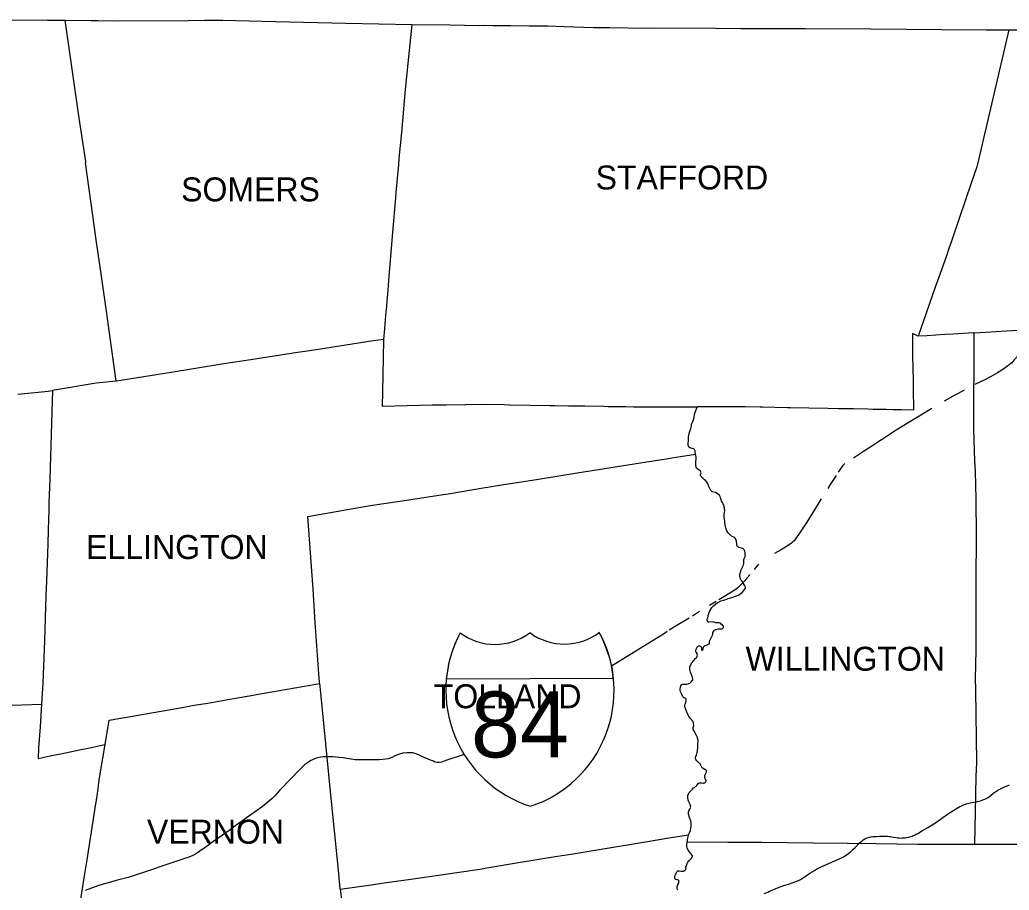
# Model space of a CAD drawing. Extents: x 0 to 2603, y -226 to 830.
# Drawn here: x 231.5 to 287.2, y 653.4 to 702.5 of the extents above; entities that cross this region are included whole.
import ezdxf

# ---------------------------------------------------------------- set-up
doc = ezdxf.new("R2010")
doc.units = 0
for name, color, linetype in [('CT_TSH_Map_Districts', 7, 'Continuous'), ('CT_TSH_Map_Interstate_Roads', 7, 'Continuous'), ('CT_TSH_Map_Town_Limits', 7, 'Continuous'), ('CT_TSH_Map_Town_Text', 7, 'Continuous'), ('CT_TSH_Map_US_and_State_Routes', 7, 'Continuous')]:
    doc.layers.add(name, color=color, linetype=linetype)

msp = doc.modelspace()

# ---------------------------------------------------------------- linework, layer by layer
at = {"layer": 'CT_TSH_Map_Districts'}
for points in [[(285.263, 684.866), (285.933, 684.911), (287.104, 684.983), (287.764, 685.023), (289.085, 685.105), (289.205, 685.102), (289.289, 685.108), (289.862, 685.118), (294.917, 685.193), (296.698, 685.197)], [(285.263, 684.866), (285.247, 682.571), (285.241, 681.474), (285.241, 680.031), (285.233, 679.443), (285.299, 677.651), (285.326, 677.079), (285.377, 675.496), (285.38, 673.452), (285.382, 672.739), (285.377, 671.584), (285.377, 668.972), (285.37, 668.249), (285.375, 667.631), (285.368, 666.987), (285.329, 665.367), (285.34, 664.78), (285.344, 664.739), (285.4, 660.656), (285.377, 659.862), (285.336, 657.85), (285.293, 656.032)], [(269.09, 656.152), (269.106, 656.26), (269.122, 656.315), (269.144, 656.453), (269.17, 656.564), (269.174, 656.574)], [(268.561, 653.446), (268.542, 653.535), (268.528, 653.59), (268.531, 653.653), (268.548, 653.719), (268.573, 653.776), (268.622, 653.858), (268.634, 653.91), (268.627, 653.991), (268.606, 654.015), (268.555, 654.032), (268.482, 654.044), (268.454, 654.054), (268.42, 654.089), (268.407, 654.112), (268.398, 654.16), (268.403, 654.233), (268.433, 654.324), (268.468, 654.405), (268.516, 654.477), (268.559, 654.521), (268.577, 654.535), (268.612, 654.548), (268.638, 654.55), (268.753, 654.518), (268.832, 654.514), (268.885, 654.522), (268.951, 654.551), (268.988, 654.578), (269.019, 654.626), (269.033, 654.689), (269.03, 654.752), (269.051, 654.842), (269.1, 654.953), (269.111, 654.992), (269.133, 655.031), (269.188, 655.108), (269.241, 655.17), (269.343, 655.253), (269.386, 655.31), (269.403, 655.349), (269.397, 655.385), (269.387, 655.405), (269.317, 655.496), (269.267, 655.552), (269.204, 655.631), (269.129, 655.745), (269.095, 655.838), (269.078, 655.916), (269.075, 656.006), (269.09, 656.152)], [(285.293, 656.032), (284.403, 656.034), (282.106, 656.032), (279.722, 656.059), (278.191, 656.087), (278.142, 656.084), (276.191, 656.107), (273.285, 656.144), (271.395, 656.143), (269.09, 656.152)]]:
    msp.add_lwpolyline(points, dxfattribs=at)
at = {"layer": 'CT_TSH_Map_Interstate_Roads'}
for p, q in [((264.952, 665.379), (255.52, 665.339)), ((242.107, 655.992), (241.385, 655.487)), ((240.221, 655.049), (239.307, 654.741)), ((237.988, 654.302), (237.872, 654.259)), ((238.627, 654.513), (237.988, 654.302)), ((236.462, 653.87), (235.985, 653.729)), ((236.911, 653.99), (236.462, 653.87))]:
    msp.add_line(p, q, dxfattribs=at)
for points in [[(288.632, 685.126), (288.156, 684.322), (287.757, 683.642), (287.653, 683.489), (287.537, 683.342), (287.478, 683.275), (287.37, 683.171), (287.172, 683.014), (287.023, 682.893), (286.838, 682.761), (286.581, 682.61), (286.2, 682.399)], [(286.2, 682.399), (285.871, 682.228), (285.314, 681.961)], [(284.706, 681.636), (284.363, 681.452), (284.185, 681.352), (283.59, 681.017)], [(282.893, 680.61), (282.792, 680.554), (282.46, 680.351), (282.022, 680.088), (281.561, 679.804), (280.884, 679.377), (280.378, 679.053), (279.74, 678.637), (279.497, 678.479)], [(279.497, 678.479), (279.249, 678.318), (279.045, 678.186), (278.69, 677.954), (278.467, 677.814)], [(277.985, 677.508), (277.959, 677.49), (277.905, 677.439), (277.867, 677.393), (277.81, 677.322), (277.731, 677.207), (277.607, 677.017)], [(277.489, 676.833), (277.164, 676.324), (277.027, 676.103)], [(276.649, 675.505), (276.323, 674.989), (275.833, 674.203)], [(275.833, 674.203), (275.434, 673.582), (275.395, 673.521), (275.212, 673.265), (275.124, 673.153), (275.061, 673.087), (274.974, 673.009), (274.841, 672.911), (274.692, 672.82), (274.394, 672.646), (274.015, 672.435)], [(273.11, 671.831), (272.87, 671.531)], [(272.646, 671.256), (272.465, 671.033), (272.341, 670.896)], [(271.851, 670.425), (271.595, 670.255), (271.067, 669.937)], [(272.341, 670.896), (272.221, 670.761), (272.071, 670.611), (271.971, 670.524), (271.851, 670.425)], [(271.067, 669.937), (270.873, 669.815)], [(270.725, 669.727), (270.346, 669.5)], [(269.201, 668.788), (268.52, 668.368)], [(269.794, 669.154), (269.395, 668.908)], [(268.52, 668.368), (268.086, 668.1)], [(267.811, 667.93), (264.836, 666.086)], [(267.977, 668.033), (267.811, 667.93)], [(248.452, 660.95), (248.242, 660.906), (248.142, 660.875)], [(248.958, 660.965), (248.775, 660.963), (248.588, 660.964), (248.452, 660.95)], [(252.349, 660.89), (252.244, 660.862), (252.093, 660.83), (251.939, 660.813), (251.729, 660.8), (251.558, 660.799), (251.07, 660.795), (250.588, 660.791), (250.454, 660.79), (250.383, 660.8), (250.277, 660.819), (250.039, 660.857), (249.896, 660.881), (249.706, 660.904), (249.47, 660.931), (249.28, 660.949), (249.12, 660.961), (249.013, 660.966), (248.958, 660.965)], [(253.821, 661.131), (253.625, 661.185), (253.477, 661.202), (253.319, 661.197), (253.07, 661.166), (252.829, 661.097), (252.609, 661.021), (252.495, 660.955), (252.349, 660.89)], [(254.634, 660.786), (254.269, 660.937), (253.821, 661.131)], [(256.525, 661.099), (255.552, 660.78), (255.243, 660.673), (255.113, 660.652), (254.998, 660.654), (254.897, 660.675), (254.79, 660.72), (254.634, 660.786)], [(247.701, 660.629), (247.533, 660.512), (247.466, 660.457), (247.406, 660.403), (247.25, 660.24), (246.759, 659.726), (246.126, 659.063), (245.848, 658.767), (245.683, 658.606)], [(248.142, 660.875), (248.057, 660.842), (247.969, 660.804), (247.882, 660.756), (247.804, 660.7), (247.701, 660.629)], [(245.683, 658.606), (245.617, 658.544), (245.462, 658.405), (245.262, 658.244), (245.14, 658.151), (244.814, 657.918), (244.567, 657.743), (244.262, 657.525)], [(244.262, 657.525), (244.037, 657.366), (243.787, 657.187), (243.524, 656.999), (243.329, 656.86)], [(243.329, 656.86), (242.901, 656.558), (242.708, 656.415)], [(242.708, 656.415), (242.364, 656.172), (242.107, 655.992)], [(241.385, 655.487), (241.23, 655.4), (241.109, 655.347), (240.889, 655.276), (240.221, 655.049)], [(237.872, 654.259), (237.587, 654.166), (236.911, 653.99)], [(239.307, 654.741), (239.12, 654.677), (238.627, 654.513)], [(235.985, 653.729), (235.614, 653.604), (235.367, 653.51), (235.17, 653.427)]]:
    msp.add_lwpolyline(points, dxfattribs=at)
for centre, radius, start, end in [((262.356, 664.719), 6.864, 151.8748, 252.2637), ((262.365, 664.715), 6.874, 151.8748, 174.7861), ((258.258, 670.571), 3.265, 233.2263, 307.1377), ((262.174, 670.589), 3.264, 233.3979, 307.1378), ((258.113, 664.699), 6.864, 288.272, 28.6609), ((258.122, 664.695), 6.864, 5.7168, 28.6609)]:
    msp.add_arc(centre, radius, start, end, dxfattribs=at)
at = {"layer": 'CT_TSH_Map_Town_Limits'}
for points in [[(216.957, 700.307), (219.751, 700.248), (221.29, 700.214), (222.262, 700.994), (222.922, 701.493), (226.979, 702.07), (230.107, 702.52), (230.118, 702.52), (233.045, 702.499), (234.019, 702.492)], [(234.019, 702.492), (235.495, 702.482), (235.713, 702.488), (235.728, 702.475), (235.876, 702.474), (237.005, 702.454), (240.968, 702.482), (241.914, 702.504), (242.915, 702.501), (242.925, 702.501), (245.895, 702.424), (249.856, 702.327), (253.576, 702.255)], [(234.019, 702.492), (234.041, 702.363), (234.355, 700.135), (234.814, 696.978), (235.185, 694.533), (235.191, 694.462)], [(253.576, 702.255), (253.206, 698.582), (252.99, 696.168), (252.849, 694.691), (252.851, 694.527)], [(253.576, 702.255), (255.71, 702.227), (257.378, 702.206), (257.592, 702.208), (258.165, 702.202), (258.908, 702.192), (258.911, 702.192), (259.143, 702.193), (260.204, 702.179), (261.248, 702.172), (262.172, 702.147), (263.839, 702.087), (264.735, 702.087), (266.786, 702.054), (266.947, 702.06), (270.692, 702.039), (272.118, 702.035), (275.574, 702.027), (275.761, 702.026), (279.456, 702.002), (283.438, 701.981), (285.954, 701.963), (287.227, 701.95)], [(287.227, 701.95), (285.533, 694.694)], [(287.227, 701.95), (288.33, 701.956), (293.654, 701.922), (296.827, 701.891), (298.059, 701.91), (298.257, 701.902), (299.351, 701.838), (299.357, 701.838), (299.361, 701.837), (300.965, 701.762), (301.321, 701.764), (301.732, 701.741), (305.24, 701.567)], [(236.912, 682.141), (236.761, 683.229), (236.483, 685.275), (236.36, 686.085), (236.1, 687.926), (235.768, 690.242), (235.695, 690.806), (235.191, 694.462)], [(251.99, 684.503), (252.048, 685.094), (252.056, 685.123), (252.064, 685.162), (252.137, 686.047), (252.162, 686.361), (252.188, 686.665), (252.242, 687.282), (252.306, 688.063), (252.507, 690.529), (252.667, 692.485), (252.691, 692.78), (252.742, 693.367), (252.768, 693.581), (252.843, 694.343), (252.851, 694.527)], [(285.533, 694.694), (285.458, 694.375), (285.415, 694.231), (285.126, 693.368), (284.418, 691.254), (284.318, 690.979), (284.192, 690.606), (283.97, 689.976), (283.85, 689.629), (283.713, 689.215), (283.636, 689.011), (283.343, 688.167), (283.082, 687.439), (282.572, 685.978), (282.121, 684.682)], [(285.263, 684.866), (285.933, 684.911), (287.104, 684.983), (287.764, 685.023), (289.085, 685.105), (289.205, 685.102), (289.289, 685.108), (289.862, 685.118), (294.917, 685.193), (296.698, 685.197)], [(251.99, 684.503), (251.393, 684.414), (248.309, 683.941), (247.42, 683.8), (247.126, 683.756), (244.503, 683.357), (242.971, 683.118), (241.272, 682.841), (240.01, 682.638), (236.938, 682.14), (236.912, 682.141)], [(251.99, 684.503), (251.987, 684.453), (251.946, 682.502), (251.927, 681.539), (251.906, 680.739), (254.73, 680.816), (255.517, 680.822), (256.59, 680.825), (256.628, 680.831), (257.685, 680.855), (258.8, 680.825), (259.077, 680.813), (261.351, 680.782), (261.635, 680.775), (262.409, 680.764), (262.715, 680.757), (263.332, 680.75), (264.408, 680.731), (264.64, 680.724), (265.633, 680.712), (266.071, 680.702), (266.137, 680.705), (266.51, 680.703), (267.583, 680.708), (269.508, 680.706), (269.655, 680.709)], [(282.121, 684.682), (281.795, 684.837), (281.804, 684.234), (281.805, 684.037), (281.805, 683.382), (281.818, 683.088), (281.819, 682.877), (281.82, 682.573), (281.832, 682.466), (281.839, 681.918), (281.84, 681.721), (281.855, 680.512), (281.171, 680.526), (280.708, 680.533), (280.309, 680.541), (279.576, 680.558), (279.288, 680.563), (278.468, 680.579), (278.414, 680.578), (277.626, 680.595), (277.016, 680.609), (275.959, 680.625), (274.927, 680.647), (274.761, 680.65), (273.344, 680.676), (273.213, 680.682), (272.369, 680.697), (271.99, 680.691), (270.901, 680.702), (269.655, 680.709)], [(285.263, 684.866), (284.065, 684.797), (283.614, 684.769), (282.602, 684.711), (282.121, 684.682)], [(285.263, 684.866), (285.247, 682.571), (285.241, 681.474), (285.241, 680.031), (285.233, 679.443), (285.299, 677.651), (285.326, 677.079), (285.377, 675.496), (285.38, 673.452), (285.382, 672.739), (285.377, 671.584), (285.377, 668.972), (285.37, 668.249), (285.375, 667.631), (285.368, 666.987), (285.329, 665.367), (285.34, 664.78), (285.344, 664.739), (285.4, 660.656), (285.377, 659.862), (285.336, 657.85), (285.293, 656.032)], [(236.912, 682.141), (235.787, 682.025), (233.319, 681.617)], [(231.371, 681.411), (233.07, 681.587), (233.319, 681.617)], [(233.319, 681.617), (233.304, 681.031), (233.168, 676.635), (233.124, 675.271), (233.113, 674.884), (233.071, 673.775), (233.05, 672.96), (232.984, 670.881), (232.951, 670.061), (232.867, 667.499), (232.816, 666.088), (232.795, 665.59), (232.778, 665.13), (232.702, 663.937)], [(269.655, 680.709), (269.598, 680.574), (269.491, 680.277), (269.482, 680.248), (269.465, 680.14), (269.465, 680.082), (269.457, 680.026), (269.44, 679.958), (269.396, 679.849), (269.337, 679.746), (269.32, 679.701), (269.318, 679.635), (269.265, 679.4), (269.222, 679.304), (269.197, 679.182), (269.165, 679.084), (269.151, 679.012), (269.158, 678.783), (269.127, 678.654), (269.14, 678.551), (269.154, 678.495), (269.188, 678.442), (269.241, 678.399), (269.364, 678.379), (269.428, 678.359), (269.474, 678.331), (269.488, 678.318), (269.512, 678.285), (269.523, 678.236), (269.525, 678.172), (269.536, 678.106), (269.558, 678.039)], [(248.386, 665.112), (248.377, 665.185), (248.336, 665.64), (248.135, 668.533), (248.008, 670.415), (247.718, 674.519), (251.225, 675.14), (252.906, 675.391), (254.009, 675.551), (255.09, 675.715), (255.621, 675.793), (257.707, 676.146), (257.864, 676.167), (258.275, 676.237), (260.612, 676.603), (263.006, 676.992), (263.253, 677.034), (264.463, 677.222), (265.16, 677.336), (265.756, 677.43), (267.43, 677.695), (267.687, 677.738), (267.939, 677.775), (268.228, 677.827), (268.715, 677.899), (269.558, 678.039)], [(270.951, 675.652), (270.91, 675.722), (270.831, 675.781), (270.734, 675.845), (270.689, 675.864), (270.528, 675.91), (270.491, 675.928), (270.448, 675.96), (270.429, 675.987), (270.376, 676.088), (270.314, 676.202), (270.276, 676.315), (270.242, 676.396), (270.202, 676.461), (270.147, 676.521), (270.072, 676.589), (270.041, 676.626), (270.014, 676.649), (269.988, 676.678), (269.924, 676.722), (269.9, 676.747), (269.867, 676.796), (269.848, 676.842), (269.848, 676.878), (269.877, 676.985), (269.872, 677.015), (269.86, 677.042), (269.839, 677.069), (269.759, 677.142), (269.719, 677.168), (269.665, 677.213), (269.647, 677.239), (269.612, 677.302), (269.587, 677.385), (269.583, 677.478), (269.584, 677.604), (269.597, 677.764), (269.595, 677.876), (269.585, 677.917), (269.558, 678.039)], [(270.53, 668.573), (270.339, 668.556), (270.294, 668.566), (270.27, 668.579), (270.241, 668.641), (270.231, 668.666), (270.233, 668.727), (270.246, 668.767), (270.256, 668.829), (270.278, 668.886), (270.285, 668.927), (270.335, 669.11), (270.368, 669.198), (270.424, 669.294), (270.51, 669.411), (270.586, 669.484), (270.81, 669.661), (270.86, 669.689), (270.987, 669.754), (271.172, 669.808), (271.215, 669.813), (271.324, 669.85), (271.416, 669.889), (271.616, 669.944), (271.767, 670.004), (271.938, 670.059), (271.988, 670.082), (272.119, 670.173), (272.193, 670.235), (272.292, 670.343), (272.352, 670.43), (272.378, 670.479), (272.382, 670.526), (272.373, 670.568), (272.337, 670.641), (272.268, 670.732), (272.171, 670.888), (272.15, 670.913), (272.125, 670.953), (272.106, 671.001), (272.08, 671.075), (272.068, 671.138), (272.069, 671.239), (272.101, 671.375), (272.142, 671.503), (272.255, 671.739), (272.281, 671.811), (272.288, 671.854), (272.294, 671.963), (272.289, 672.043), (272.291, 672.101), (272.305, 672.151), (272.355, 672.223), (272.371, 672.27), (272.371, 672.297), (272.36, 672.352), (272.359, 672.419), (272.365, 672.453), (272.362, 672.489), (272.341, 672.571), (272.306, 672.639), (272.274, 672.679), (272.223, 672.713), (272.156, 672.739), (272.012, 672.769), (271.982, 672.787), (271.944, 672.819), (271.922, 672.844), (271.901, 672.912), (271.9, 672.956), (271.875, 673.126), (271.854, 673.189), (271.846, 673.231), (271.806, 673.293), (271.761, 673.329), (271.68, 673.366), (271.599, 673.412), (271.53, 673.472), (271.411, 673.604), (271.356, 673.678), (271.342, 673.718), (271.315, 673.753), (271.268, 673.876), (271.254, 673.963), (271.235, 674.053), (271.228, 674.176), (271.216, 674.264), (271.201, 674.347), (271.18, 674.487), (271.179, 674.666), (271.205, 674.747), (271.215, 674.826), (271.195, 674.995), (271.181, 675.039), (271.161, 675.13), (271.122, 675.232), (271.084, 675.314), (271.039, 675.392), (270.988, 675.52), (270.981, 675.562), (270.951, 675.652)], [(268.994, 664.266), (268.893, 664.31), (268.865, 664.343), (268.838, 664.387), (268.749, 664.583), (268.741, 664.61), (268.715, 664.658), (268.707, 664.694), (268.707, 664.763), (268.725, 664.916), (268.746, 664.976), (268.775, 665.029), (268.802, 665.054), (268.849, 665.066), (269.086, 665.067), (269.154, 665.076), (269.196, 665.095), (269.25, 665.124), (269.341, 665.212), (269.386, 665.278), (269.407, 665.31), (269.407, 665.344), (269.393, 665.467), (269.386, 665.5), (269.318, 665.641), (269.284, 665.737), (269.246, 665.893), (269.238, 665.984), (269.246, 666.048), (269.283, 666.141), (269.364, 666.264), (269.456, 666.378), (269.591, 666.533), (269.618, 666.556), (269.635, 666.586), (269.662, 666.648), (269.672, 666.708), (269.668, 666.737), (269.651, 666.786), (269.619, 666.848), (269.584, 666.895), (269.578, 666.925), (269.576, 666.976), (269.606, 667.043), (269.646, 667.121), (269.686, 667.18), (269.73, 667.223), (269.754, 667.229), (269.799, 667.223), (269.848, 667.205), (269.87, 667.187), (269.886, 667.166), (269.9, 667.112), (269.895, 667.04), (269.899, 667.015), (269.912, 666.997), (269.932, 666.983), (269.952, 666.98), (269.965, 666.985), (269.98, 667.001), (270.005, 667.051), (270.02, 667.131), (270.041, 667.187), (270.069, 667.221), (270.107, 667.242), (270.188, 667.263), (270.233, 667.281), (270.343, 667.331), (270.354, 667.346), (270.346, 667.411), (270.348, 667.438), (270.356, 667.474), (270.381, 667.52), (270.393, 667.573), (270.44, 667.671), (270.506, 667.784), (270.525, 667.825), (270.542, 667.889), (270.551, 667.97), (270.581, 668.035), (270.643, 668.1), (270.711, 668.141), (270.742, 668.153), (270.85, 668.182), (270.976, 668.176), (271.013, 668.179), (271.058, 668.193), (271.093, 668.21), (271.121, 668.238), (271.138, 668.275), (271.144, 668.299), (271.139, 668.333), (271.129, 668.356), (271.116, 668.376), (271.07, 668.427), (271.022, 668.456), (270.981, 668.497), (270.961, 668.509), (270.909, 668.522), (270.705, 668.532), (270.53, 668.573)], [(236.288, 661.67), (236.518, 663.03), (240.426, 663.714), (241.426, 663.892), (242.073, 664.003), (243.32, 664.222), (244.286, 664.388), (244.421, 664.415), (244.816, 664.477), (248.276, 665.089), (248.386, 665.112)], [(249.542, 653.499), (249.447, 654.578), (248.994, 659.008), (248.441, 664.57), (248.386, 665.112)], [(269.174, 656.574), (269.204, 656.652), (269.278, 656.808), (269.307, 656.925), (269.324, 657.095), (269.317, 657.241), (269.294, 657.36), (269.236, 657.545), (269.174, 657.738), (269.169, 657.815), (269.175, 657.869), (269.198, 657.927), (269.243, 658.009), (269.269, 658.049), (269.295, 658.126), (269.293, 658.194), (269.284, 658.238), (269.189, 658.437), (269.158, 658.523), (269.125, 658.694), (269.136, 658.791), (269.169, 658.891), (269.203, 658.949), (269.265, 659.019), (269.322, 659.076), (269.388, 659.147), (269.459, 659.216), (269.536, 659.263), (269.574, 659.29), (269.598, 659.309), (269.635, 659.351), (269.709, 659.464), (269.764, 659.498), (269.818, 659.509), (269.901, 659.503), (270.019, 659.485), (270.038, 659.489), (270.049, 659.494), (270.065, 659.496), (270.091, 659.507), (270.14, 659.551), (270.156, 659.579), (270.16, 659.609), (270.159, 659.648), (270.104, 659.734), (270.09, 659.793), (270.084, 659.867), (270.088, 659.922), (270.108, 659.974), (270.185, 660.115), (270.191, 660.162), (270.183, 660.195), (270.175, 660.212), (270.153, 660.232), (270.122, 660.245), (270.075, 660.256), (269.971, 660.325), (269.94, 660.355), (269.896, 660.429), (269.824, 660.581), (269.803, 660.592), (269.765, 660.602), (269.712, 660.659), (269.641, 660.746), (269.58, 660.826), (269.562, 660.867), (269.558, 660.913), (269.592, 660.993), (269.619, 661.052), (269.648, 661.131), (269.682, 661.316), (269.696, 661.522), (269.695, 661.726), (269.715, 661.838), (269.714, 661.902), (269.687, 662.012), (269.672, 662.062), (269.622, 662.171), (269.482, 662.415), (269.449, 662.475), (269.426, 662.569), (269.434, 662.618), (269.464, 662.74), (269.454, 662.847), (269.426, 662.954), (269.391, 662.999), (269.255, 663.161), (269.197, 663.245), (269.178, 663.291), (269.157, 663.326), (269.061, 663.536), (268.986, 663.742), (268.964, 663.818), (268.964, 663.864), (268.983, 663.938), (269.023, 664.038), (269.04, 664.106), (269.037, 664.197), (269.031, 664.222), (269.012, 664.252), (268.994, 664.266)], [(214.877, 663.569), (215.278, 663.543), (216.439, 663.482), (217.207, 663.433), (218.922, 663.489), (219.76, 663.52), (221.073, 663.557), (223.183, 663.63), (226.522, 663.732), (227.338, 663.762), (227.894, 663.775), (228.395, 663.794), (228.896, 663.807), (231.591, 663.896), (232.702, 663.937)], [(232.702, 663.937), (232.621, 662.668), (232.539, 661.469), (232.509, 660.88), (233.183, 661.022), (234.048, 661.199), (234.847, 661.364), (235.519, 661.499), (235.847, 661.571), (236.288, 661.67)], [(234.817, 652.292), (234.861, 652.571), (235.106, 654.143), (235.272, 655.158), (235.712, 657.956), (235.852, 658.874), (235.954, 659.648), (236.012, 660.014), (236.288, 661.67)], [(249.542, 653.499), (251.279, 653.75), (252.143, 653.879), (253.527, 654.077), (257.545, 654.663), (257.8, 654.703), (259.598, 655.007), (261.654, 655.342), (262.666, 655.506), (262.775, 655.523), (263.692, 655.678), (266.861, 656.192), (268.06, 656.395), (269.174, 656.574)], [(269.09, 656.152), (269.106, 656.26), (269.122, 656.315), (269.144, 656.453), (269.17, 656.564), (269.174, 656.574)], [(268.561, 653.446), (268.542, 653.535), (268.528, 653.59), (268.531, 653.653), (268.548, 653.719), (268.573, 653.776), (268.622, 653.858), (268.634, 653.91), (268.627, 653.991), (268.606, 654.015), (268.555, 654.032), (268.482, 654.044), (268.454, 654.054), (268.42, 654.089), (268.407, 654.112), (268.398, 654.16), (268.403, 654.233), (268.433, 654.324), (268.468, 654.405), (268.516, 654.477), (268.559, 654.521), (268.577, 654.535), (268.612, 654.548), (268.638, 654.55), (268.753, 654.518), (268.832, 654.514), (268.885, 654.522), (268.951, 654.551), (268.988, 654.578), (269.019, 654.626), (269.033, 654.689), (269.03, 654.752), (269.051, 654.842), (269.1, 654.953), (269.111, 654.992), (269.133, 655.031), (269.188, 655.108), (269.241, 655.17), (269.343, 655.253), (269.386, 655.31), (269.403, 655.349), (269.397, 655.385), (269.387, 655.405), (269.317, 655.496), (269.267, 655.552), (269.204, 655.631), (269.129, 655.745), (269.095, 655.838), (269.078, 655.916), (269.075, 656.006), (269.09, 656.152)], [(285.293, 656.032), (284.403, 656.034), (282.106, 656.032), (279.722, 656.059), (278.191, 656.087), (278.142, 656.084), (276.191, 656.107), (273.285, 656.144), (271.395, 656.143), (269.09, 656.152)], [(294.601, 656.015), (290.108, 656.021), (289.178, 656.017), (285.293, 656.032)], [(249.542, 653.499), (250.093, 649.168)]]:
    msp.add_lwpolyline(points, dxfattribs=at)
at = {"layer": 'CT_TSH_Map_US_and_State_Routes'}
for p, q in [((279.57, 656.468), (279.675, 656.474)), ((279.675, 656.474), (279.794, 656.48)), ((281.387, 656.407), (281.46, 656.416)), ((277.937, 655.357), (278.212, 655.544)), ((274.548, 653.708), (274.612, 653.732)), ((274.612, 653.732), (274.863, 653.811)), ((274.863, 653.811), (274.958, 653.844)), ((274.958, 653.844), (275.079, 653.886)), ((275.079, 653.886), (275.228, 653.94))]:
    msp.add_line(p, q, dxfattribs=at)
for points in [[(285.979, 658.634), (286.058, 658.685), (286.167, 658.764), (286.29, 658.865), (286.383, 658.936), (286.505, 659.021), (286.616, 659.087), (286.757, 659.163), (286.902, 659.233), (287.044, 659.297), (287.271, 659.395)], [(283.089, 657.256), (283.502, 657.542), (283.828, 657.768), (284.134, 657.961), (284.285, 658.054), (284.47, 658.16), (284.532, 658.192), (284.558, 658.204)], [(284.558, 658.204), (284.619, 658.24), (284.688, 658.268)], [(284.688, 658.268), (284.819, 658.317), (284.967, 658.358), (285.162, 658.401)], [(285.162, 658.401), (285.249, 658.412), (285.471, 658.457), (285.62, 658.497), (285.681, 658.512), (285.758, 658.538), (285.867, 658.577), (285.979, 658.634)], [(282.366, 656.808), (282.67, 656.987), (282.913, 657.138), (283.089, 657.256)], [(278.212, 655.544), (278.302, 655.617), (278.424, 655.723), (278.557, 655.852), (278.694, 655.997), (278.792, 656.097), (278.882, 656.179), (278.962, 656.241), (279.026, 656.288), (279.111, 656.338), (279.166, 656.366), (279.239, 656.4), (279.3, 656.422), (279.386, 656.443), (279.457, 656.458), (279.57, 656.468)], [(279.794, 656.48), (279.934, 656.487), (280.394, 656.489)], [(280.394, 656.489), (280.483, 656.481), (280.544, 656.474), (280.729, 656.435)], [(280.729, 656.435), (280.837, 656.415), (280.946, 656.402), (281.018, 656.395), (281.065, 656.394)], [(281.46, 656.416), (281.546, 656.432), (281.64, 656.456), (281.772, 656.497), (281.844, 656.526)], [(281.844, 656.526), (281.957, 656.575), (282.046, 656.625)], [(282.046, 656.625), (282.089, 656.645), (282.366, 656.808)], [(281.065, 656.394), (281.171, 656.39), (281.243, 656.395), (281.387, 656.407)], [(276.691, 654.791), (277.421, 655.107), (277.718, 655.246), (277.937, 655.357)], [(275.823, 654.269), (275.937, 654.349), (276.017, 654.406), (276.142, 654.493), (276.265, 654.566), (276.327, 654.605), (276.446, 654.671), (276.525, 654.711), (276.691, 654.791)], [(275.228, 653.94), (275.366, 654), (275.483, 654.056), (275.585, 654.111), (275.698, 654.183), (275.823, 654.269)], [(273.441, 653.266), (273.636, 653.348), (273.745, 653.397), (273.89, 653.459), (274.06, 653.529), (274.188, 653.581), (274.548, 653.708)]]:
    msp.add_lwpolyline(points, dxfattribs=at)

# ---------------------------------------------------------------- texts
at = {"layer": 'CT_TSH_Map_Interstate_Roads'}
msp.add_text('84', height=3.7137, dxfattribs=at).set_placement((256.91, 660.938))
at = {"layer": 'CT_TSH_Map_Town_Text'}
for s, p in [('STAFFORD', (263.937, 692.955)), ('SOMERS', (240.573, 692.284)), ('ELLINGTON', (235.218, 672.121)), ('WILLINGTON', (272.392, 665.822)), ('TOLLAND', (254.813, 663.708)), ('VERNON', (238.647, 656.072))]:
    msp.add_text(s, height=1.35, dxfattribs=at).set_placement(p)

doc.saveas('drawing.dxf')
